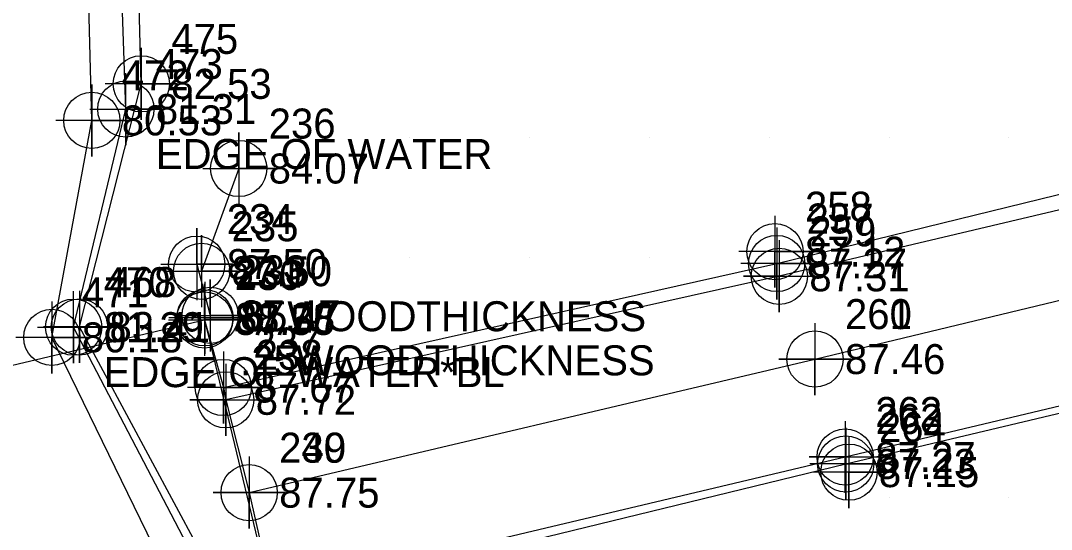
# Model space of a CAD drawing. Extents: x 1988140 to 1988766, y 249950 to 250250.
# Drawn here: x 1988457.6 to 1988543.5, y 250067.3 to 250109.7 of the extents above; entities that cross this region are included whole.
import ezdxf

# ---------------------------------------------------------------- set-up
doc = ezdxf.new("R2010")
doc.units = 0
for name, color, linetype in [('Exist DTM Breakline', 7, 'Continuous'), ('Exist DTM Breakline Cogo Elevation', 7, 'Continuous'), ('Exist DTM Breakline Cogo Number', 7, 'Continuous'), ('Exist DTM Breakline Cogo Point CELL', 7, 'Continuous'), ('Exist DTM Breakline Underwater', 7, 'Continuous'), ('Exist DTM Crownline', 7, 'Continuous'), ('Exist DTM Crownline Cogo Elevation', 7, 'Continuous'), ('Exist DTM Crownline Cogo Number', 7, 'Continuous'), ('Exist DTM Crownline Cogo Point CELL', 7, 'Continuous'), ('Exist DTM QL2 LIDAR Elevation Point', 7, 'Continuous'), ('Exist DTM Regular Point CELL', 7, 'Continuous'), ('Exist DTM Regular Point Cogo Elevation', 7, 'Continuous'), ('Exist DTM Regular Point Cogo Number', 7, 'Continuous'), ('Exist Hydro Stream or Body of Water', 7, 'Continuous'), ('Exist Hydro Stream or Body of Water Cogo Comment', 7, 'Continuous'), ('Exist Hydro Stream or Body of Water Cogo Elevation', 7, 'Continuous'), ('Exist Hydro Stream or Body of Water Cogo Number', 7, 'Continuous'), ('Exist Hydro Stream or Body of Water Cogo Point CELL', 7, 'Continuous'), ('Exist Roads Change in Surface', 7, 'Continuous'), ('Exist Roads EOP', 7, 'Continuous'), ('Exist Roads EOP Cogo Elevation', 7, 'Continuous'), ('Exist Roads EOP Cogo Number', 7, 'Continuous'), ('Exist Roads EOP Cogo Point CELL', 7, 'Continuous'), ('Exist Roads EOT', 7, 'Continuous'), ('Exist Roads EOT Cogo Elevation', 7, 'Continuous'), ('Exist Roads EOT Cogo Number', 7, 'Continuous'), ('Exist Roads EOT Cogo Point CELL', 7, 'Continuous'), ('Exist Structure Major Bridge WW', 7, 'Continuous'), ('Exist Structure Major Deck Tunnel Box Culvert', 7, 'Continuous'), ('Exist Structure Major Deck Tunnel Box Culvert Cogo Elevation', 7, 'Continuous'), ('Exist Structure Major Deck Tunnel Box Culvert Cogo Number', 7, 'Continuous'), ('Exist Structure Major Deck Tunnel Box Culvert Cogo Point CELL', 7, 'Continuous'), ('Exist Structure Minor Head and End Wall Cogo Comment', 7, 'Continuous'), ('Exist Structure Minor Head and End Wall Cogo Elevation', 7, 'Continuous'), ('Exist Structure Minor Head and End Wall Cogo Number', 7, 'Continuous'), ('Exist Structure Minor Head and End Wall Cogo Point CELL', 7, 'Continuous')]:
    doc.layers.add(name, color=color, linetype=linetype)

msp = doc.modelspace()

# ---------------------------------------------------------------- linework, layer by layer
at = {"layer": 'Exist DTM Breakline'}
msp.add_lwpolyline([(1988502.0577, 249958.2531), (1988491.6502, 249990.2233), (1988485.1148, 250021.3111), (1988477.2086, 250042.1909), (1988478.2961, 250054.8431), (1988462.5221, 250084.1865), (1988467.6761, 250104.4545), (1988466.937, 250133.0471)], dxfattribs=at)
at = {"layer": 'Exist DTM Breakline Cogo Point CELL'}
for points in [[(1988467.6761, 250107.4545), (1988467.6761, 250101.4545), (1988467.6761, 250104.4545), (1988470.6761, 250104.4545), (1988464.6761, 250104.4545)], [(1988463.5509, 250104.4082), (1988463.5509, 250098.4082), (1988463.5509, 250101.4082), (1988466.5509, 250101.4082), (1988460.5509, 250101.4082)], [(1988462.5221, 250087.1865), (1988462.5221, 250081.1865), (1988462.5221, 250084.1865), (1988465.5221, 250084.1865), (1988459.5221, 250084.1865)], [(1988460.2177, 250086.319), (1988460.2177, 250080.319), (1988460.2177, 250083.319), (1988463.2177, 250083.319), (1988457.2177, 250083.319)]]:
    msp.add_lwpolyline(points, dxfattribs=at)
for centre in [(1988467.6761, 250104.4545), (1988463.5509, 250101.4082), (1988462.5221, 250084.1865), (1988460.2177, 250083.319)]:
    msp.add_circle(centre, 2.344, dxfattribs=at)
at = {"layer": 'Exist DTM Breakline Underwater'}
msp.add_lwpolyline([(1988472.6196, 250042.0736), (1988475.5478, 250051.8121), (1988460.2177, 250083.319), (1988463.5509, 250101.4082), (1988462.7669, 250131.4643), (1988448.9433, 250161.2866), (1988447.9748, 250187.7776)], dxfattribs=at)
at = {"layer": 'Exist DTM Crownline'}
msp.add_lwpolyline([(1988476.6655, 250070.3758), (1988523.8279, 250081.5102), (1988587.4445, 250096.8162)], dxfattribs=at)
at = {"layer": 'Exist DTM Crownline Cogo Point CELL'}
for points in [[(1988523.8279, 250084.5102), (1988523.8279, 250078.5102), (1988523.8279, 250081.5102), (1988526.8279, 250081.5102), (1988520.8279, 250081.5102)], [(1988476.6655, 250073.3758), (1988476.6655, 250067.3758), (1988476.6655, 250070.3758), (1988479.6655, 250070.3758), (1988473.6655, 250070.3758)]]:
    msp.add_lwpolyline(points, dxfattribs=at)
for centre in [(1988523.8279, 250081.5102), (1988476.6655, 250070.3758)]:
    msp.add_circle(centre, 2.344, dxfattribs=at)
at = {"layer": 'Exist DTM QL2 LIDAR Elevation Point'}
for p, q in [((1988470, 250100), (1988470, 250100)), ((1988480, 250100), (1988480, 250100)), ((1988490, 250100), (1988490, 250100)), ((1988500, 250100), (1988500, 250100)), ((1988510, 250100), (1988510, 250100)), ((1988520, 250100), (1988520, 250100)), ((1988530, 250100), (1988530, 250100)), ((1988540, 250100), (1988540, 250100)), ((1988480, 250090), (1988480, 250090)), ((1988490, 250090), (1988490, 250090)), ((1988500, 250090), (1988500, 250090)), ((1988510, 250090), (1988510, 250090)), ((1988530, 250070), (1988530, 250070)), ((1988540, 250070), (1988540, 250070))]:
    msp.add_line(p, q, dxfattribs=at)
at = {"layer": 'Exist DTM Regular Point CELL'}
for points in [[(1988520.4917, 250093.4664), (1988520.4917, 250087.4664), (1988520.4917, 250090.4664), (1988523.4917, 250090.4664), (1988517.4917, 250090.4664)], [(1988526.6553, 250075.0851), (1988526.6553, 250069.0851), (1988526.6553, 250072.0851), (1988529.6553, 250072.0851), (1988523.6553, 250072.0851)]]:
    msp.add_lwpolyline(points, dxfattribs=at)
for centre in [(1988520.4917, 250090.4664), (1988526.6553, 250072.0851)]:
    msp.add_circle(centre, 2.344, dxfattribs=at)
at = {"layer": 'Exist Hydro Stream or Body of Water'}
msp.add_lwpolyline([(1988474.7634, 250042.2609), (1988477.3409, 250054.8476), (1988462.0354, 250084.1709), (1988466.3899, 250102.3572), (1988465.3709, 250132.3106), (1988450.4249, 250163.1283), (1988449.3573, 250188.3896)], dxfattribs=at)
at = {"layer": 'Exist Hydro Stream or Body of Water Cogo Point CELL'}
for points in [[(1988463.3899, 250102.3572), (1988469.3899, 250102.3572), (1988466.3899, 250102.3572), (1988466.3899, 250099.3572), (1988466.3899, 250105.3572)], [(1988459.0354, 250084.1709), (1988465.0354, 250084.1709), (1988462.0354, 250084.1709), (1988462.0354, 250081.1709), (1988462.0354, 250087.1709)]]:
    msp.add_lwpolyline(points, dxfattribs=at)
for centre in [(1988466.3899, 250102.3572), (1988462.0354, 250084.1709)]:
    msp.add_circle(centre, 2.344, dxfattribs=at)
at = {"layer": 'Exist Roads Change in Surface'}
msp.add_lwpolyline([(1988472.9466, 250084.7703), (1988474.5186, 250079.1384), (1988474.7146, 250078.1173), (1988476.6655, 250070.3758), (1988478.5507, 250062.0221), (1988478.7113, 250061.1525), (1988479.6615, 250056.5423)], dxfattribs=at)
at = {"layer": 'Exist Roads EOP'}
for points in [[(1988474.5186, 250079.1384), (1988520.6371, 250089.4794), (1988585.1885, 250105.299), (1988653.4927, 250121.1544), (1988721.8388, 250137.0511), (1988746.7518, 250142.7981)], [(1988478.7113, 250061.1525), (1988526.3961, 250072.7689), (1988588.4517, 250087.5135), (1988658.4677, 250104.3569), (1988725.1723, 250119.8591), (1988750.1331, 250125.8579)]]:
    msp.add_lwpolyline(points, dxfattribs=at)
at = {"layer": 'Exist Roads EOP Cogo Point CELL'}
for points in [[(1988520.6371, 250092.4794), (1988520.6371, 250086.4794), (1988520.6371, 250089.4794), (1988523.6371, 250089.4794), (1988517.6371, 250089.4794)], [(1988472.9779, 250087.9505), (1988472.9779, 250081.9505), (1988472.9779, 250084.9505), (1988475.9779, 250084.9505), (1988469.9779, 250084.9505)], [(1988474.5186, 250082.1384), (1988474.5186, 250076.1384), (1988474.5186, 250079.1384), (1988477.5186, 250079.1384), (1988471.5186, 250079.1384)], [(1988526.3961, 250075.7689), (1988526.3961, 250069.7689), (1988526.3961, 250072.7689), (1988529.3961, 250072.7689), (1988523.3961, 250072.7689)]]:
    msp.add_lwpolyline(points, dxfattribs=at)
for centre in [(1988520.6371, 250089.4794), (1988472.9779, 250084.9505), (1988474.5186, 250079.1384), (1988526.3961, 250072.7689)]:
    msp.add_circle(centre, 2.344, dxfattribs=at)
at = {"layer": 'Exist Roads EOT'}
for points in [[(1988747.017, 250141.8392), (1988721.8571, 250135.9434), (1988653.8188, 250120.1043), (1988585.7363, 250103.7612), (1988520.8576, 250088.4105), (1988474.7146, 250078.1173)], [(1988478.5507, 250062.0221), (1988526.3466, 250073.3488), (1988588.4376, 250088.1415), (1988658.1757, 250104.9714), (1988725.0188, 250120.3526), (1988749.8922, 250126.2558)]]:
    msp.add_lwpolyline(points, dxfattribs=at)
at = {"layer": 'Exist Roads EOT Cogo Point CELL'}
for points in [[(1988520.8576, 250091.4105), (1988520.8576, 250085.4105), (1988520.8576, 250088.4105), (1988517.8576, 250088.4105), (1988523.8576, 250088.4105)], [(1988523.8279, 250084.5102), (1988523.8279, 250078.5102), (1988523.8279, 250081.5102), (1988520.8279, 250081.5102), (1988526.8279, 250081.5102)], [(1988474.7146, 250081.1173), (1988474.7146, 250075.1173), (1988474.7146, 250078.1173), (1988471.7146, 250078.1173), (1988477.7146, 250078.1173)], [(1988526.3466, 250076.3488), (1988526.3466, 250070.3488), (1988526.3466, 250073.3488), (1988523.3466, 250073.3488), (1988529.3466, 250073.3488)], [(1988476.6655, 250073.3758), (1988476.6655, 250067.3758), (1988476.6655, 250070.3758), (1988473.6655, 250070.3758), (1988479.6655, 250070.3758)]]:
    msp.add_lwpolyline(points, dxfattribs=at)
for centre in [(1988520.8576, 250088.4105), (1988523.8279, 250081.5102), (1988474.7146, 250078.1173), (1988526.3466, 250073.3488), (1988476.6655, 250070.3758)]:
    msp.add_circle(centre, 2.344, dxfattribs=at)
at = {"layer": 'Exist Structure Major Bridge WW'}
for p, q in [((1988475.7946, 250097.3957), (1988472.7029, 250088.8328)), ((1988472.3016, 250089.4274), (1988473.4166, 250085.1562))]:
    msp.add_line(p, q, dxfattribs=at)
at = {"layer": 'Exist Structure Major Deck Tunnel Box Culvert'}
msp.add_lwpolyline([(1988414.7923, 250071.0539), (1988472.9466, 250084.7703), (1988479.6979, 250056.7161), (1988421.5011, 250042.945)], close=True, dxfattribs=at)
at = {"layer": 'Exist Structure Major Deck Tunnel Box Culvert Cogo Point CELL'}
msp.add_lwpolyline([(1988469.9466, 250084.7703), (1988475.9466, 250084.7703), (1988472.9466, 250084.7703), (1988472.9466, 250087.7703), (1988472.9466, 250081.7703)], dxfattribs=at)
msp.add_circle((1988472.9466, 250084.7703), 2.344, dxfattribs=at)
at = {"layer": 'Exist Structure Minor Head and End Wall Cogo Point CELL'}
for points in [[(1988472.7946, 250097.3957), (1988478.7946, 250097.3957), (1988475.7946, 250097.3957), (1988475.7946, 250100.3957), (1988475.7946, 250094.3957)], [(1988469.3016, 250089.4274), (1988475.3016, 250089.4274), (1988472.3016, 250089.4274), (1988472.3016, 250092.4274), (1988472.3016, 250086.4274)], [(1988469.7029, 250088.8328), (1988475.7029, 250088.8328), (1988472.7029, 250088.8328), (1988472.7029, 250091.8328), (1988472.7029, 250085.8328)], [(1988470.4166, 250085.1562), (1988476.4166, 250085.1562), (1988473.4166, 250085.1562), (1988473.4166, 250088.1562), (1988473.4166, 250082.1562)]]:
    msp.add_lwpolyline(points, dxfattribs=at)
for centre in [(1988475.7946, 250097.3957), (1988472.3016, 250089.4274), (1988472.7029, 250088.8328), (1988473.4166, 250085.1562)]:
    msp.add_circle(centre, 2.344, dxfattribs=at)

# ---------------------------------------------------------------- texts
at = {"layer": 'Exist DTM Breakline Cogo Elevation'}
for s, p in [('82.53', (1988470.1761, 250103.2045)), ('80.53', (1988466.0509, 250100.1582)), ('83.41', (1988465.0221, 250082.9365)), ('80.18', (1988462.7177, 250082.069))]:
    msp.add_text(s, height=2.5, dxfattribs=at).set_placement(p)
at = {"layer": 'Exist DTM Breakline Cogo Number'}
for s, p in [('475', (1988470.1761, 250106.9545)), ('472', (1988466.0509, 250103.9082)), ('468', (1988465.0221, 250086.6865)), ('471', (1988462.7177, 250085.819))]:
    msp.add_text(s, height=2.5, dxfattribs=at).set_placement(p)
at = {"layer": 'Exist DTM Crownline Cogo Elevation'}
for s, p in [('87.46', (1988526.3279, 250080.2602)), ('87.75', (1988479.1655, 250069.1258))]:
    msp.add_text(s, height=2.5, dxfattribs=at).set_placement(p)
at = {"layer": 'Exist DTM Crownline Cogo Number'}
for s, p in [('261', (1988526.3279, 250084.0102)), ('240', (1988479.1655, 250072.8758))]:
    msp.add_text(s, height=2.5, dxfattribs=at).set_placement(p)
at = {"layer": 'Exist DTM Regular Point Cogo Elevation'}
for s, p in [('87.12', (1988522.9917, 250089.2164)), ('87.15', (1988529.1553, 250070.8351))]:
    msp.add_text(s, height=2.5, dxfattribs=at).set_placement(p)
at = {"layer": 'Exist DTM Regular Point Cogo Number'}
for s, p in [('258', (1988522.9917, 250092.9664)), ('264', (1988529.1553, 250074.5851))]:
    msp.add_text(s, height=2.5, dxfattribs=at).set_placement(p)
at = {"layer": 'Exist Hydro Stream or Body of Water Cogo Comment'}
for s, p in [('EDGE OF WATER', (1988468.8899, 250097.3572)), ('EDGE OF WATER*BL', (1988464.5354, 250079.1709))]:
    msp.add_text(s, height=2.5, dxfattribs=at).set_placement(p)
at = {"layer": 'Exist Hydro Stream or Body of Water Cogo Elevation'}
for s, p in [('81.31', (1988468.8899, 250101.1072)), ('81.29', (1988464.5354, 250082.9209))]:
    msp.add_text(s, height=2.5, dxfattribs=at).set_placement(p)
at = {"layer": 'Exist Hydro Stream or Body of Water Cogo Number'}
for s, p in [('473', (1988468.8899, 250104.8572)), ('470', (1988464.5354, 250086.6709))]:
    msp.add_text(s, height=2.5, dxfattribs=at).set_placement(p)
at = {"layer": 'Exist Roads EOP Cogo Elevation'}
for s, p in [('87.27', (1988523.1371, 250088.2294)), ('88.28', (1988475.4779, 250083.7005)), ('87.67', (1988477.0186, 250077.8884)), ('87.23', (1988528.8961, 250071.5189))]:
    msp.add_text(s, height=2.5, dxfattribs=at).set_placement(p)
at = {"layer": 'Exist Roads EOP Cogo Number'}
for s, p in [('257', (1988523.1371, 250091.9794)), ('231', (1988475.4779, 250087.4505)), ('237', (1988477.0186, 250081.6384)), ('263', (1988528.8961, 250075.2689))]:
    msp.add_text(s, height=2.5, dxfattribs=at).set_placement(p)
at = {"layer": 'Exist Roads EOT Cogo Elevation'}
for s, p in [('87.31', (1988523.3576, 250087.1605)), ('87.46', (1988526.3279, 250080.2602)), ('87.72', (1988477.2146, 250076.8673)), ('87.27', (1988528.8466, 250072.0988)), ('87.75', (1988479.1655, 250069.1258))]:
    msp.add_text(s, height=2.5, dxfattribs=at).set_placement(p)
at = {"layer": 'Exist Roads EOT Cogo Number'}
for s, p in [('259', (1988523.3576, 250090.9105)), ('260', (1988526.3279, 250084.0102)), ('238', (1988477.2146, 250080.6173)), ('262', (1988528.8466, 250075.8488)), ('239', (1988479.1655, 250072.8758))]:
    msp.add_text(s, height=2.5, dxfattribs=at).set_placement(p)
at = {"layer": 'Exist Structure Major Deck Tunnel Box Culvert Cogo Elevation'}
msp.add_text('87.55', height=2.5, dxfattribs=at).set_placement((1988475.4466, 250083.5203))
at = {"layer": 'Exist Structure Major Deck Tunnel Box Culvert Cogo Number'}
msp.add_text('230', height=2.5, dxfattribs=at).set_placement((1988475.4466, 250087.2703))
at = {"layer": 'Exist Structure Minor Head and End Wall Cogo Comment'}
for s, p in [('.65WOODTHICKNESS', (1988475.2029, 250083.8328)), ('.25WOODTHICKNESS', (1988475.9166, 250080.1562))]:
    msp.add_text(s, height=2.5, dxfattribs=at).set_placement(p)
at = {"layer": 'Exist Structure Minor Head and End Wall Cogo Elevation'}
for s, p in [('84.07', (1988478.2946, 250096.1457)), ('87.50', (1988474.8016, 250088.1774)), ('87.50', (1988475.2029, 250087.5828)), ('87.47', (1988475.9166, 250083.9062))]:
    msp.add_text(s, height=2.5, dxfattribs=at).set_placement(p)
at = {"layer": 'Exist Structure Minor Head and End Wall Cogo Number'}
for s, p in [('236', (1988478.2946, 250099.8957)), ('234', (1988474.8016, 250091.9274)), ('235', (1988475.2029, 250091.3328)), ('233', (1988475.9166, 250087.6562))]:
    msp.add_text(s, height=2.5, dxfattribs=at).set_placement(p)

doc.saveas('drawing.dxf')
